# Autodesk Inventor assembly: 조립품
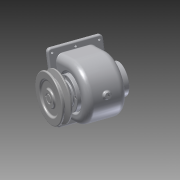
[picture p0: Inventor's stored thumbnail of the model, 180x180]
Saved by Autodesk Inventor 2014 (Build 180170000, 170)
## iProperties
Created: 2015-09
Part Number: 조립품
Document SubType Name: Assembly
Designer: Owner
Author: Owner
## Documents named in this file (13)
- C:\Documents and Settings\Owner\바탕 화면\450907V1024\조립품.iam
- C:\Documents and Settings\Owner\바탕 화면\450907V1024\축.ipt
- C:\Documents and Settings\Owner\바탕 화면\450907V1024\키 - 5 x 5 x 18.ipt
- C:\Documents and Settings\Owner\바탕 화면\450907V1024\키 - 6 x 6 x 22.ipt
- C:\Documents and Settings\Owner\바탕 화면\450907V1024\베어링 6203.ipt
- C:\Documents and Settings\Owner\바탕 화면\450907V1024\본체.ipt
- C:\Documents and Settings\Owner\바탕 화면\450907V1024\뒤커버.ipt
- C:\Documents and Settings\Owner\바탕 화면\450907V1024\앞커버.ipt
- C:\Documents and Settings\Owner\바탕 화면\450907V1024\오일 실 17 32 8.ipt
- C:\Documents and Settings\Owner\바탕 화면\450907V1024\스퍼기어.ipt
- C:\Documents and Settings\Owner\바탕 화면\450907V1024\V-벨트풀리.ipt
- C:\Documents and Settings\Owner\바탕 화면\450907V1024\멈춤나사 - M4x10.ipt
- C:\Documents and Settings\Owner\바탕 화면\450907V1024\볼트 M3 x 8.ipt
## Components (9 placed, 2 different names)
1. V-벨트풀리:1 — 강체:1
2. ISO 4762 M3 x 8:2
3. ISO 4762 M3 x 8:1
4. ISO 4762 M3 x 8:3
5. ISO 4762 M3 x 8:4
6. ISO 4762 M3 x 8:5
7. ISO 4762 M3 x 8:6
8. ISO 4762 M3 x 8:7
9. ISO 4762 M3 x 8:8
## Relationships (1: WeldJoint 1)
- 강체:1 [WeldJoint]: V-벨트풀리:1
